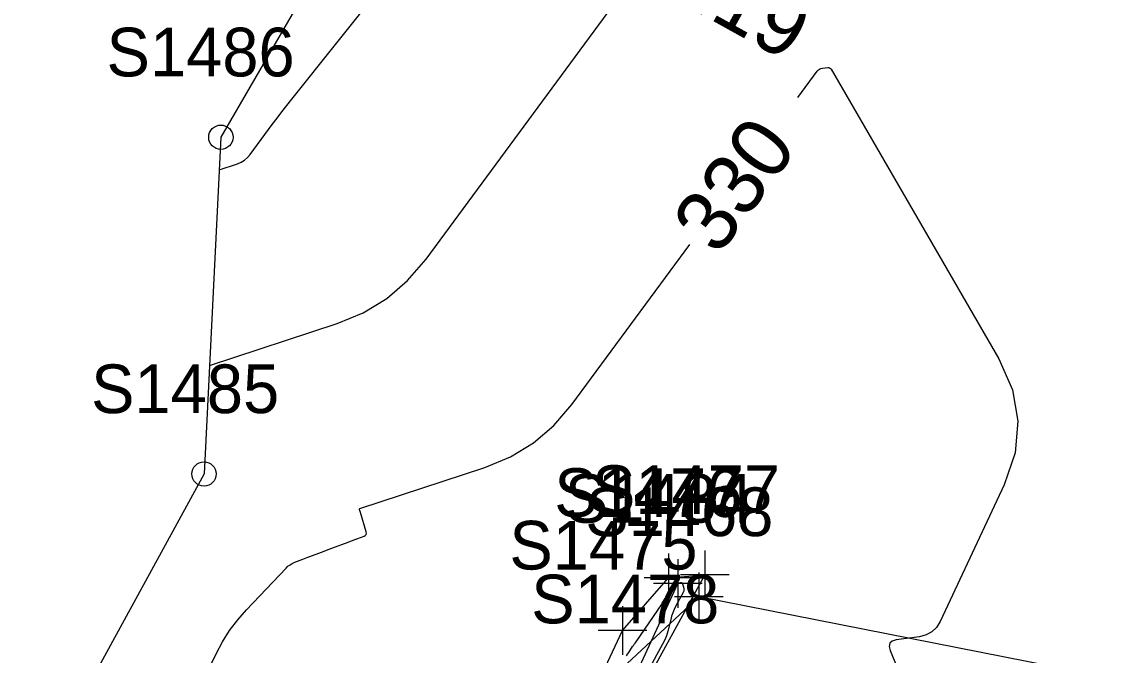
# Model space of a CAD drawing. Extents: x 816928 to 825690, y 436959 to 448212.
# Drawn here: x 819193.5 to 819282.5, y 445763 to 445815.1 of the extents above; entities that cross this region are included whole.
import ezdxf

# ---------------------------------------------------------------- set-up
doc = ezdxf.new("R2010")
doc.units = 0
for name, color, linetype in [('DESIGN - SCRATCH - User 1', 7, 'Continuous'), ('SURVEY - CENTERLINE - Preliminary Curve Text', 7, 'Continuous'), ('SURVEY - CONTOURS - Index with Text', 7, 'Continuous'), ('SURVEY - CONTOURS - Intermediate with optional Text', 7, 'Continuous'), ('SURVEY - DTM - Breaklines', 7, 'Continuous'), ('SURVEY - DTM - Breaklines - Points - Locators', 7, 'Continuous'), ('SURVEY - DTM - Breaklines - Points - Numbers', 7, 'Continuous'), ('SURVEY - DTM - Spot Points - Locators', 7, 'Continuous'), ('SURVEY - DTM - Spot Points - Point Numbers', 7, 'Continuous'), ('SURVEY - NON-TRANSPORTATION - Features', 7, 'Continuous'), ('SURVEY - NON-TRANSPORTATION - Features - Points - Locators', 7, 'Continuous'), ('SURVEY - NON-TRANSPORTATION - Features - Points - Numbers', 7, 'Continuous')]:
    doc.layers.add(name, color=color, linetype=linetype)

msp = doc.modelspace()

# ---------------------------------------------------------------- linework, layer by layer
at = {"layer": 'DESIGN - SCRATCH - User 1'}
msp.add_lwpolyline([(819229.368, 445839.151), (819209.91, 445805.584), (819208.53, 445777.911), (819187.332, 445739.191)], dxfattribs=at)
at = {"layer": 'SURVEY - CONTOURS - Index with Text'}
for points in [[(819257.353, 445808.856), (819258.944, 445811.015), (819259.029, 445811.111), (819259.128, 445811.183), (819259.24, 445811.233), (819259.365, 445811.26), (819259.797, 445811.311), (819259.883, 445811.31), (819259.959, 445811.287), (819260.022, 445811.241), (819260.075, 445811.172), (819273.867, 445787.365), (819274.992, 445784.826), (819275.442, 445782.257), (819275.216, 445779.659), (819274.314, 445777.032), (819269.036, 445765.777), (819268.742, 445765.297), (819268.365, 445764.931), (819267.903, 445764.679), (819267.358, 445764.541), (819265.439, 445764.276), (819265.099, 445764.179), (819264.902, 445763.999), (819264.847, 445763.738), (819264.934, 445763.396), (819274.916, 445739.205)], [(819198.415, 445740.294), (819209.527, 445763.138), (819210.047, 445764.111), (819210.635, 445765.035), (819211.293, 445765.912), (819212.019, 445766.741), (819215.273, 445770.181), (819215.43, 445770.329), (819215.599, 445770.456), (819215.783, 445770.564), (819215.979, 445770.651), (819216.644, 445770.902), (819216.786, 445770.956), (819216.929, 445771.01), (819217.071, 445771.064), (819217.214, 445771.118), (819218.19, 445771.487), (819218.399, 445771.566), (819218.608, 445771.645), (819218.817, 445771.724), (819219.026, 445771.803), (819220.382, 445772.316), (819220.561, 445772.384), (819220.74, 445772.451), (819220.919, 445772.519), (819221.098, 445772.587), (819221.682, 445772.808), (819221.787, 445772.865), (819221.851, 445772.943), (819221.874, 445773.041), (819221.857, 445773.159), (819221.39, 445774.735), (819221.379, 445774.772), (819221.368, 445774.81), (819221.356, 445774.847), (819221.345, 445774.885), (819221.309, 445775.008), (819221.305, 445775.032), (819221.31, 445775.051), (819221.324, 445775.067), (819221.345, 445775.077), (819231.62, 445778.452), (819233.718, 445779.318), (819235.61, 445780.47), (819237.294, 445781.907), (819238.772, 445783.63), (819248.457, 445796.779)]]:
    msp.add_lwpolyline(points, dxfattribs=at)
at = {"layer": 'SURVEY - CONTOURS - Intermediate with optional Text'}
for points in [[(819209.776, 445802.912), (819211.272, 445803.403), (819211.577, 445803.529), (819211.852, 445803.697), (819212.098, 445803.906), (819212.313, 445804.157), (819214.136, 445806.632), (819214.529, 445807.16), (819214.927, 445807.685), (819215.331, 445808.205), (819215.739, 445808.722), (819237.939, 445836.517)], [(819208.975, 445786.831), (819219.47, 445790.279), (819221.613, 445791.163), (819223.545, 445792.34), (819225.266, 445793.808), (819226.776, 445795.568), (819242.506, 445816.924), (819243.789, 445818.648), (819245.089, 445820.359), (819246.405, 445822.058), (819247.738, 445823.744), (819253.998, 445831.581)], [(819243.251, 445762.964), (819243.349, 445763.107), (819243.446, 445763.251), (819243.765, 445763.72), (819243.833, 445763.821), (819243.902, 445763.921), (819243.971, 445764.021), (819244.04, 445764.121), (819245.834, 445766.715), (819245.928, 445766.854), (819246.021, 445766.995), (819246.111, 445767.138), (819246.198, 445767.283), (819246.48, 445767.757), (819246.542, 445767.858), (819246.607, 445767.957), (819246.674, 445768.054), (819246.744, 445768.149), (819247.284, 445768.864), (819247.293, 445768.877), (819247.302, 445768.889), (819247.31, 445768.902), (819247.317, 445768.915), (819247.341, 445768.959), (819247.347, 445768.967), (819247.354, 445768.973), (819247.362, 445768.977), (819247.372, 445768.979), (819247.694, 445769.006), (819247.756, 445769.002), (819247.806, 445768.981), (819247.843, 445768.941), (819247.868, 445768.884), (819247.966, 445768.52), (819247.979, 445768.443), (819247.978, 445768.368), (819247.963, 445768.294), (819247.932, 445768.222), (819247.298, 445767.023), (819247.17, 445766.763), (819247.06, 445766.497), (819246.967, 445766.224), (819246.892, 445765.944), (819246.669, 445765.001), (819246.615, 445764.801), (819246.548, 445764.607), (819246.468, 445764.417), (819246.375, 445764.232), (819244.871, 445761.458)]]:
    msp.add_lwpolyline(points, dxfattribs=at)
at = {"layer": 'SURVEY - DTM - Breaklines'}
for points in [[(819233.429, 445718.602), (819229.956, 445719.219), (819227.425, 445720.331), (819227.123, 445729.197), (819231.37, 445740.375), (819242.919, 445765.06), (819246.716, 445769.382), (819249.706, 445769.619), (819244.758, 445760.636), (819240.694, 445750.791), (819235.615, 445723.376)], [(819232.568, 445722.77), (819235.103, 445736.136), (819240.565, 445753.895), (819247.471, 445768.901)]]:
    msp.add_lwpolyline(points, dxfattribs=at)
at = {"layer": 'SURVEY - DTM - Breaklines - Points - Locators'}
for p, q in [((819246.716, 445771.382), (819246.716, 445767.382)), ((819249.706, 445771.619), (819249.706, 445767.619)), ((819247.471, 445770.901), (819247.471, 445766.901)), ((819248.716, 445769.382), (819244.716, 445769.382)), ((819251.706, 445769.619), (819247.706, 445769.619)), ((819249.471, 445768.901), (819245.471, 445768.901)), ((819242.919, 445767.06), (819242.919, 445763.06)), ((819244.919, 445765.06), (819240.919, 445765.06))]:
    msp.add_line(p, q, dxfattribs=at)
at = {"layer": 'SURVEY - DTM - Spot Points - Locators'}
for centre in [(819209.91, 445805.584), (819208.53, 445777.911)]:
    msp.add_circle(centre, 1, dxfattribs=at)
at = {"layer": 'SURVEY - NON-TRANSPORTATION - Features'}
msp.add_lwpolyline([(819351.494, 445767.604), (819341.921, 445749.552), (819249.204, 445767.807), (819214.983, 445735.979)], dxfattribs=at)
at = {"layer": 'SURVEY - NON-TRANSPORTATION - Features - Points - Locators'}
for p, q in [((819249.204, 445769.807), (819249.204, 445765.807)), ((819251.204, 445767.807), (819247.204, 445767.807))]:
    msp.add_line(p, q, dxfattribs=at)

# ---------------------------------------------------------------- texts
at = {"layer": 'SURVEY - CENTERLINE - Preliminary Curve Text'}
msp.add_text('PT 64+18.19', height=5, rotation=330.93226, dxfattribs=at).set_placement((819222.839, 445830.441))
at = {"layer": 'SURVEY - CONTOURS - Index with Text'}
msp.add_text('330', height=5, rotation=53.62472, dxfattribs=at).set_placement((819250.798, 445795.742))
at = {"layer": 'SURVEY - DTM - Breaklines - Points - Numbers'}
for s, p in [('S1476', (819237.318, 445774.382)), ('S1477', (819240.419, 445774.619)), ('S1484', (819238.183, 445773.901)), ('S1475', (819233.631, 445770.06)), ('S1478', (819235.423, 445765.636))]:
    msp.add_text(s, height=4, dxfattribs=at).set_placement(p)
at = {"layer": 'SURVEY - DTM - Spot Points - Point Numbers'}
for s, p in [('S1486', (819200.512, 445810.584)), ('S1485', (819199.242, 445782.911))]:
    msp.add_text(s, height=4, dxfattribs=at).set_placement(p)
at = {"layer": 'SURVEY - NON-TRANSPORTATION - Features - Points - Numbers'}
msp.add_text('S1468', height=4, dxfattribs=at).set_placement((819239.869, 445772.807))

doc.saveas('drawing.dxf')
